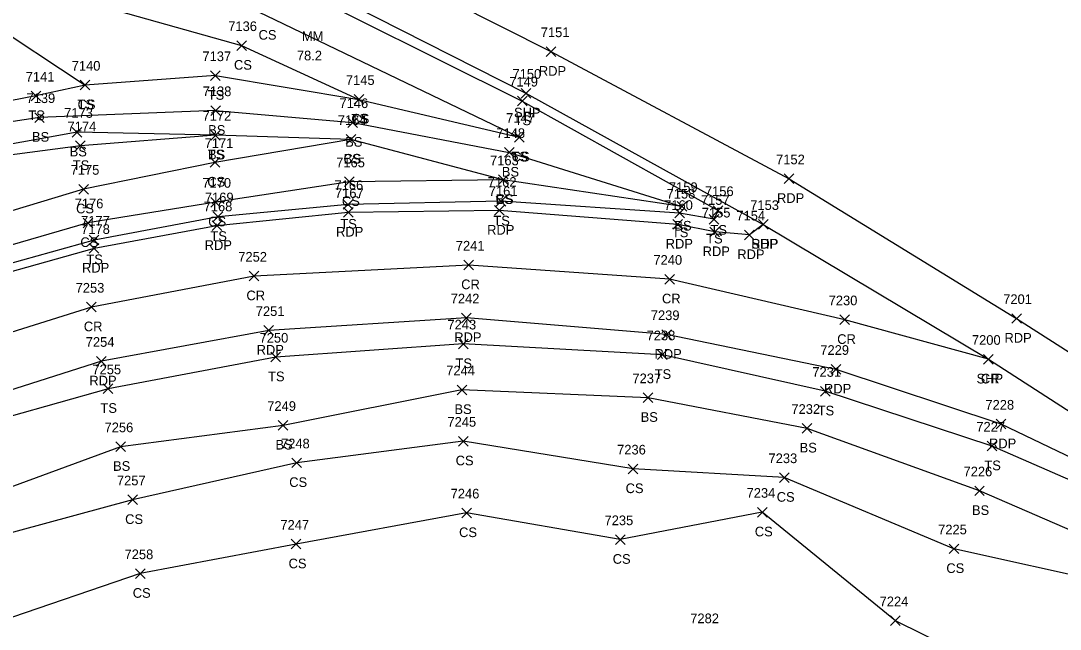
# Model space of a CAD drawing. Extents: x 1505656 to 1508446, y 700805 to 703031.
# Drawn here: x 1508114 to 1508329.4, y 701312.1 to 701438.1 of the extents above; entities that cross this region are included whole.
import ezdxf

# ---------------------------------------------------------------- set-up
doc = ezdxf.new("R2010")
doc.units = 0
for name, color, linetype in [('L_A', 7, 'Continuous'), ('L_I', 7, 'Continuous'), ('L_TIC', 7, 'Continuous'), ('LELB', 7, 'Continuous'), ('P_A', 7, 'Continuous'), ('P_I', 7, 'Continuous'), ('P_TIC', 7, 'Continuous'), ('PET', 7, 'Continuous'), ('PRC', 7, 'Continuous'), ('PSP', 7, 'Continuous'), ('S_A', 7, 'Continuous'), ('S_C', 7, 'Continuous')]:
    doc.layers.add(name, color=color, linetype=linetype)

msp = doc.modelspace()

# ---------------------------------------------------------------- linework, layer by layer
at = {"layer": 'L_TIC'}
for points in [[(1508158.76, 701432), (1508160.76, 701434)], [(1508160.76, 701432), (1508158.76, 701434)], [(1508153.35, 701425.77), (1508155.35, 701427.77)], [(1508155.35, 701425.77), (1508153.35, 701427.77)], [(1508153.35, 701425.77), (1508155.35, 701427.77)], [(1508155.35, 701425.77), (1508153.35, 701427.77)], [(1508126.36, 701423.8), (1508128.36, 701425.8)], [(1508128.36, 701423.8), (1508126.36, 701425.8)], [(1508126.36, 701423.8), (1508128.36, 701425.8)], [(1508128.36, 701423.8), (1508126.36, 701425.8)], [(1508116.18, 701421.55), (1508118.18, 701423.55)], [(1508118.18, 701421.55), (1508116.18, 701423.55)], [(1508183.08, 701420.84), (1508185.08, 701422.84)], [(1508185.08, 701420.84), (1508183.08, 701422.84)], [(1508183.08, 701420.84), (1508185.08, 701422.84)], [(1508185.08, 701420.84), (1508183.08, 701422.84)], [(1508216.92, 701420.51), (1508218.92, 701422.51)], [(1508218.92, 701420.51), (1508216.92, 701422.51)], [(1508116.91, 701417.09), (1508118.91, 701419.09)], [(1508118.91, 701417.09), (1508116.91, 701419.09)], [(1508153.4, 701418.52), (1508155.4, 701420.52)], [(1508155.4, 701418.52), (1508153.4, 701420.52)], [(1508153.4, 701418.52), (1508155.4, 701420.52)], [(1508155.4, 701418.52), (1508153.4, 701420.52)], [(1508181.8, 701416.05), (1508183.8, 701418.05)], [(1508183.8, 701416.05), (1508181.8, 701418.05)], [(1508124.71, 701414.04), (1508126.71, 701416.04)], [(1508126.71, 701414.04), (1508124.71, 701416.04)], [(1508153.37, 701413.42), (1508155.37, 701415.42)], [(1508155.37, 701413.42), (1508153.37, 701415.42)], [(1508153.37, 701413.42), (1508155.37, 701415.42)], [(1508155.37, 701413.42), (1508153.37, 701415.42)], [(1508216.28, 701413), (1508218.28, 701415)], [(1508218.28, 701413), (1508216.28, 701415)], [(1508216.28, 701413), (1508218.28, 701415)], [(1508218.28, 701413), (1508216.28, 701415)], [(1508125.4, 701411.23), (1508127.4, 701413.23)], [(1508127.4, 701411.23), (1508125.4, 701413.23)], [(1508181.44, 701412.55), (1508183.44, 701414.55)], [(1508183.44, 701412.55), (1508181.44, 701414.55)], [(1508181.44, 701412.55), (1508183.44, 701414.55)], [(1508183.44, 701412.55), (1508181.44, 701414.55)], [(1508214.23, 701409.85), (1508216.23, 701411.85)], [(1508216.23, 701409.85), (1508214.23, 701411.85)], [(1508153.24, 701407.79), (1508155.24, 701409.79)], [(1508155.24, 701407.79), (1508153.24, 701409.79)], [(1508212.98, 701404.2), (1508214.98, 701406.2)], [(1508214.98, 701404.2), (1508212.98, 701406.2)], [(1508212.98, 701404.2), (1508214.98, 701406.2)], [(1508214.98, 701404.2), (1508212.98, 701406.2)], [(1508126.05, 701402.24), (1508128.05, 701404.24)], [(1508128.05, 701402.24), (1508126.05, 701404.24)], [(1508181.11, 701403.78), (1508183.11, 701405.78)], [(1508183.11, 701403.78), (1508181.11, 701405.78)], [(1508212.52, 701399.74), (1508214.52, 701401.74)], [(1508214.52, 701399.74), (1508212.52, 701401.74)], [(1508153.42, 701399.55), (1508155.42, 701401.55)], [(1508155.42, 701399.55), (1508153.42, 701401.55)], [(1508180.82, 701399.08), (1508182.82, 701401.08)], [(1508182.82, 701399.08), (1508180.82, 701401.08)], [(1508250, 701398.68), (1508252, 701400.68)], [(1508252, 701398.68), (1508250, 701400.68)], [(1508257.5, 701397.83), (1508259.5, 701399.83)], [(1508259.5, 701397.83), (1508257.5, 701399.83)], [(1508257.5, 701397.83), (1508259.5, 701399.83)], [(1508259.5, 701397.83), (1508257.5, 701399.83)], [(1508153.92, 701396.54), (1508155.92, 701398.54)], [(1508155.92, 701396.54), (1508153.92, 701398.54)], [(1508249.51, 701397.31), (1508251.51, 701399.31)], [(1508251.51, 701397.31), (1508249.51, 701399.31)], [(1508256.61, 701396.01), (1508258.61, 701398.01)], [(1508258.61, 701396.01), (1508256.61, 701398.01)], [(1508126.94, 701395.28), (1508128.94, 701397.28)], [(1508128.94, 701395.28), (1508126.94, 701397.28)], [(1508128.22, 701391.72), (1508130.22, 701393.72)], [(1508130.22, 701391.72), (1508128.22, 701393.72)], [(1508204.68, 701370.2), (1508206.68, 701372.2)], [(1508206.68, 701370.2), (1508204.68, 701372.2)], [(1508165.85, 701367.48), (1508167.85, 701369.48)], [(1508167.85, 701367.48), (1508165.85, 701369.48)], [(1508245.94, 701367.96), (1508247.94, 701369.96)], [(1508247.94, 701367.96), (1508245.94, 701369.96)], [(1508131.13, 701360.93), (1508133.13, 701362.93)], [(1508133.13, 701360.93), (1508131.13, 701362.93)], [(1508204.43, 701360.69), (1508206.43, 701362.69)], [(1508206.43, 701360.69), (1508204.43, 701362.69)], [(1508243, 701359.07), (1508245, 701361.07)], [(1508245, 701359.07), (1508243, 701361.07)], [(1508279.7, 701360.4), (1508281.7, 701362.4)], [(1508281.7, 701360.4), (1508279.7, 701362.4)], [(1508167.36, 701353.34), (1508169.36, 701355.34)], [(1508169.36, 701353.34), (1508167.36, 701355.34)], [(1508275.93, 701352.72), (1508277.93, 701354.72)], [(1508277.93, 701352.72), (1508275.93, 701354.72)], [(1508133.71, 701348.92), (1508135.71, 701350.92)], [(1508135.71, 701348.92), (1508133.71, 701350.92)], [(1508204.68, 701350.06), (1508206.68, 701352.06)], [(1508206.68, 701350.06), (1508204.68, 701352.06)], [(1508314.24, 701349.05), (1508316.24, 701351.05)], [(1508316.24, 701349.05), (1508314.24, 701351.05)], [(1508170.2, 701345.58), (1508172.2, 701347.58)], [(1508172.2, 701345.58), (1508170.2, 701347.58)], [(1508239.89, 701344.31), (1508241.89, 701346.31)], [(1508241.89, 701344.31), (1508239.89, 701346.31)], [(1508271.19, 701342.52), (1508273.19, 701344.52)], [(1508273.19, 701342.52), (1508271.19, 701344.52)], [(1508311.64, 701339.78), (1508313.64, 701341.78)], [(1508313.64, 701339.78), (1508311.64, 701341.78)], [(1508136.21, 701337.92), (1508138.21, 701339.92)], [(1508138.21, 701337.92), (1508136.21, 701339.92)], [(1508205.39, 701335.2), (1508207.39, 701337.2)], [(1508207.39, 701335.2), (1508205.39, 701337.2)], [(1508266.65, 701335.35), (1508268.65, 701337.35)], [(1508268.65, 701335.35), (1508266.65, 701337.35)], [(1508170.07, 701328.74), (1508172.07, 701330.74)], [(1508172.07, 701328.74), (1508170.07, 701330.74)], [(1508237.22, 701329.67), (1508239.22, 701331.67)], [(1508239.22, 701329.67), (1508237.22, 701331.67)], [(1508306.33, 701327.77), (1508308.33, 701329.77)], [(1508308.33, 701327.77), (1508306.33, 701329.77)], [(1508137.79, 701322.63), (1508139.79, 701324.63)], [(1508139.79, 701322.63), (1508137.79, 701324.63)], [(1508294.21, 701312.88), (1508296.21, 701314.88)], [(1508296.21, 701312.88), (1508294.21, 701314.88)]]:
    msp.add_lwpolyline(points, dxfattribs=at)
at = {"layer": 'LELB'}
for points in [[(1507330.99, 701644.33), (1507331.57, 701641.78), (1507371.77, 701640.82), (1507418.46, 701636.99), (1507454.87, 701633.93), (1507504.71, 701630.03), (1507556.91, 701624.43), (1507606.36, 701618.24), (1507661.13, 701610.06), (1507708.24, 701601.04), (1507762.71, 701589.7), (1507814.48, 701577.03), (1507868.53, 701563.07), (1507920.81, 701547.22), (1507968.27, 701530.82), (1508018.88, 701511.91), (1508073.65, 701490), (1508121.33, 701468.38), (1508166.06, 701447.38), (1508217.92, 701421.51), (1508258.5, 701398.83)], [(1507371.82, 701631.2), (1507419.37, 701631.63), (1507454.54, 701624.79), (1507505.05, 701622.5), (1507556.06, 701615.76), (1507605.29, 701610.61), (1507659.37, 701602.95), (1507705.7, 701593), (1507760.19, 701582.5), (1507867, 701555.37), (1507918.17, 701539.42), (1507965.63, 701522.2), (1508016.59, 701504.14), (1508070.8, 701481.77), (1508118.11, 701461.28), (1508164.85, 701439.21), (1508217.28, 701414)], [(1507454.54, 701624.79), (1507504.74, 701612.91), (1507553.31, 701603.43), (1507603.85, 701602.08), (1507655.97, 701590.04), (1507703.48, 701579.9), (1507760.64, 701566.79), (1507809, 701557.31), (1507862.6, 701540.85), (1507913.87, 701525.11), (1507961.41, 701507.74), (1508011.25, 701488.42), (1508064.95, 701467.68), (1508110.8, 701446.82), (1508159.76, 701433), (1508184.08, 701421.84)], [(1507553.31, 701603.43), (1507601.29, 701589.31), (1507651.17, 701577.15), (1507700.01, 701567.77), (1507706.67, 701566.48), (1507755.13, 701548.25), (1507804.73, 701537.71), (1507857.08, 701521.39), (1507908.09, 701506.28), (1507956.13, 701490.86), (1508006.59, 701471.95), (1508058.56, 701454.54), (1508106.68, 701438.49), (1508127.36, 701424.8)], [(1508154.35, 701426.77), (1508127.36, 701424.8), (1508117.18, 701422.55), (1508087.33, 701416.79), (1508064.83, 701410.79), (1508066.66, 701419.74), (1508059.3, 701421.35), (1508054.24, 701408.37), (1508038.64, 701402.52), (1508017.45, 701393.31), (1507999.23, 701386.55), (1508004.56, 701399.96), (1508002.66, 701415), (1508002.64, 701414.99), (1507982.45, 701429.7), (1507948.4, 701442.92), (1507895.43, 701458.86), (1507841.28, 701473.44), (1507789.73, 701489.92), (1507749.11, 701498.17), (1507698.99, 701517.09)], [(1508154.4, 701419.52), (1508117.91, 701418.09), (1508089.24, 701413.76), (1508080.06, 701410.17), (1508061.42, 701406.62), (1508063.71, 701416.27), (1508061.94, 701416.78), (1508055.79, 701407.35), (1508040.19, 701400.53), (1508018.4, 701391.4), (1508000.84, 701382.32), (1507989.42, 701382.89), (1507991.8, 701393.99), (1507993.42, 701406.89), (1507988.68, 701409.34), (1507981.01, 701410.1), (1507940.5, 701420.91), (1507888, 701436.83), (1507832, 701451.94), (1507780.89, 701466.06), (1507743.18, 701476.74), (1507690.02, 701491.91)], [(1508154.35, 701426.77), (1508184.08, 701421.84), (1508217.28, 701414)], [(1508154.4, 701419.52), (1508182.8, 701417.05), (1508215.23, 701410.85), (1508251, 701399.68), (1508213.98, 701405.2), (1508182.44, 701413.55), (1508154.37, 701414.42), (1508125.71, 701415.04), (1508096.26, 701409.76), (1508073.75, 701404.93), (1508062.94, 701402.24), (1508041.57, 701393.41), (1508020.15, 701386.08), (1508000.78, 701379.38), (1507984.9, 701371.99), (1507974.85, 701354.32), (1507965.1, 701336.98)], [(1508154.37, 701414.42), (1508126.4, 701412.23), (1508096.45, 701408.26), (1508071.13, 701402.05), (1508062.75, 701400.33), (1508044.7, 701391.76), (1508020.88, 701383.6), (1508002.23, 701372.66), (1507989.78, 701369), (1507979.3, 701351.16), (1507969.45, 701332.86)], [(1508182.44, 701413.55), (1508154.24, 701408.79), (1508127.05, 701403.24), (1508100.22, 701395.21), (1508075.33, 701393.9), (1508052.69, 701378.8), (1508028.82, 701363.66)], [(1508213.98, 701405.2), (1508182.11, 701404.78), (1508154.42, 701400.55), (1508127.94, 701396.28), (1508101.95, 701388.78), (1508081.59, 701382.53), (1508058.12, 701371.27), (1508033.98, 701358.66)], [(1508258.5, 701398.83), (1508257.61, 701397.01), (1508250.51, 701398.31), (1508213.52, 701400.74), (1508181.82, 701400.08), (1508154.92, 701397.54), (1508129.22, 701392.72), (1508102.47, 701385.22), (1508082.88, 701378.2), (1508059.61, 701368.36), (1508035.53, 701355.4)], [(1508431.77, 701280.78), (1508387.5, 701311.78), (1508348.97, 701335.33), (1508315.24, 701350.05), (1508280.7, 701361.4), (1508246.94, 701368.96), (1508205.68, 701371.2), (1508166.85, 701368.48), (1508132.13, 701361.93), (1508090.91, 701350.28), (1508068.59, 701339.2), (1508045.2, 701325.84)], [(1508427.04, 701274.81), (1508383.39, 701305.02), (1508343.87, 701327.27), (1508312.64, 701340.78), (1508276.93, 701353.72), (1508244, 701360.07), (1508205.43, 701361.69), (1508168.36, 701354.34), (1508134.71, 701349.92), (1508097.62, 701336.28), (1508074.24, 701329.1), (1508053.07, 701314.95)], [(1508414.72, 701258.98), (1508371.7, 701288.23), (1508339.69, 701321.62), (1508307.33, 701328.77), (1508272.19, 701343.52), (1508240.89, 701345.31), (1508205.68, 701351.06), (1508171.2, 701346.58), (1508137.21, 701338.92), (1508101.29, 701329.16), (1508076.83, 701322.26), (1508059.02, 701305.56)], [(1508401.54, 701242.66), (1508359.95, 701269.54), (1508323.47, 701299.9), (1508295.21, 701313.88), (1508267.65, 701336.35), (1508238.22, 701330.67), (1508206.39, 701336.2), (1508171.07, 701329.74), (1508138.79, 701323.63), (1508109.62, 701313.71), (1508081.24, 701310.41), (1508068.11, 701293.32)]]:
    msp.add_lwpolyline(points, dxfattribs=at)
at = {"layer": 'P_TIC'}
for points in [[(1508222.87, 701430.74), (1508224.87, 701432.74)], [(1508224.87, 701430.74), (1508222.87, 701432.74)], [(1508217.67, 701422.12), (1508219.67, 701424.12)], [(1508219.67, 701422.12), (1508217.67, 701424.12)], [(1508272.2, 701404.41), (1508274.2, 701406.41)], [(1508274.2, 701404.41), (1508272.2, 701406.41)], [(1508212.15, 701397.84), (1508214.15, 701399.84)], [(1508214.15, 701397.84), (1508212.15, 701399.84)], [(1508180.86, 701397.44), (1508182.86, 701399.44)], [(1508182.86, 701397.44), (1508180.86, 701399.44)], [(1508153.65, 701394.67), (1508155.65, 701396.67)], [(1508155.65, 701394.67), (1508153.65, 701396.67)], [(1508249.14, 701394.96), (1508251.14, 701396.96)], [(1508251.14, 701394.96), (1508249.14, 701396.96)], [(1508256.79, 701393.39), (1508258.79, 701395.39)], [(1508258.79, 701393.39), (1508256.79, 701395.39)], [(1508266.84, 701394.95), (1508268.84, 701396.95)], [(1508268.84, 701394.95), (1508266.84, 701396.95)], [(1508266.84, 701394.95), (1508268.84, 701396.95)], [(1508268.84, 701394.95), (1508266.84, 701396.95)], [(1508263.97, 701392.77), (1508265.97, 701394.77)], [(1508265.97, 701392.77), (1508263.97, 701394.77)], [(1508128.23, 701389.98), (1508130.23, 701391.98)], [(1508130.23, 701389.98), (1508128.23, 701391.98)], [(1508205.84, 701386.54), (1508207.84, 701388.54)], [(1508207.84, 701386.54), (1508205.84, 701388.54)], [(1508161.35, 701384.25), (1508163.35, 701386.25)], [(1508163.35, 701384.25), (1508161.35, 701386.25)], [(1508247.43, 701383.6), (1508249.43, 701385.6)], [(1508249.43, 701383.6), (1508247.43, 701385.6)], [(1508127.66, 701377.83), (1508129.66, 701379.83)], [(1508129.66, 701377.83), (1508127.66, 701379.83)], [(1508205.34, 701375.59), (1508207.34, 701377.59)], [(1508207.34, 701375.59), (1508205.34, 701377.59)], [(1508283.73, 701375.21), (1508285.73, 701377.21)], [(1508285.73, 701375.21), (1508283.73, 701377.21)], [(1508319.32, 701375.47), (1508321.32, 701377.47)], [(1508321.32, 701375.47), (1508319.32, 701377.47)], [(1508164.4, 701372.99), (1508166.4, 701374.99)], [(1508166.4, 701372.99), (1508164.4, 701374.99)], [(1508246.82, 701372.14), (1508248.82, 701374.14)], [(1508248.82, 701372.14), (1508246.82, 701374.14)], [(1508129.75, 701366.61), (1508131.75, 701368.61)], [(1508131.75, 701366.61), (1508129.75, 701368.61)], [(1508313.49, 701367.02), (1508315.49, 701369.02)], [(1508315.49, 701367.02), (1508313.49, 701369.02)], [(1508313.49, 701367.02), (1508315.49, 701369.02)], [(1508315.49, 701367.02), (1508313.49, 701369.02)], [(1508281.93, 701364.94), (1508283.93, 701366.94)], [(1508283.93, 701364.94), (1508281.93, 701366.94)], [(1508316.12, 701353.6), (1508318.12, 701355.6)], [(1508318.12, 701353.6), (1508316.12, 701355.6)]]:
    msp.add_lwpolyline(points, dxfattribs=at)
at = {"layer": 'PET'}
for points in [[(1507331.09, 701648.62), (1507371.38, 701647.72), (1507419.18, 701645.9), (1507454.47, 701643.92), (1507505.5, 701639.83), (1507558.24, 701634.71), (1507608.33, 701628.44), (1507662.88, 701620.32), (1507710.96, 701611.67), (1507764.19, 701600.14), (1507816.88, 701587.97), (1507871.99, 701573.08), (1507923.59, 701557.41), (1507972.42, 701540.77), (1508022.2, 701522.45), (1508077.84, 701500.13), (1508126.28, 701479.21), (1508172.23, 701457.76), (1508223.87, 701431.74), (1508273.2, 701405.41), (1508320.32, 701376.47), (1508371.41, 701343.81), (1508408.57, 701317.59), (1508442.85, 701293.88)], [(1508267.84, 701395.95), (1508264.97, 701393.77), (1508257.79, 701394.39), (1508250.14, 701395.96), (1508213.15, 701398.84), (1508181.86, 701398.44), (1508154.65, 701395.67), (1508129.23, 701390.98), (1508103.36, 701383.73), (1508083.42, 701376.64), (1508060.29, 701366.64), (1508036.04, 701354.24)], [(1508433.77, 701283.19), (1508388.89, 701313.87), (1508350.43, 701338.64), (1508317.12, 701354.6), (1508282.93, 701365.94), (1508247.82, 701373.14), (1508206.34, 701376.59), (1508165.4, 701373.99), (1508130.75, 701367.61), (1508088.47, 701354.16), (1508065.37, 701344.9), (1508042.81, 701329.23)]]:
    msp.add_lwpolyline(points, dxfattribs=at)
at = {"layer": 'PRC'}
msp.add_lwpolyline([(1508314.49, 701368.02), (1508284.73, 701376.21), (1508248.43, 701384.6), (1508206.84, 701387.54), (1508162.35, 701385.25), (1508128.66, 701378.83), (1508083.35, 701364.58), (1508061.08, 701354.73), (1508034.54, 701339.84)], dxfattribs=at)
at = {"layer": 'PSP'}
msp.add_lwpolyline([(1507708.42, 701603.34), (1507763.41, 701591.78), (1507815.2, 701579.55), (1507869.54, 701564.45), (1507921.6, 701549.15), (1507968.74, 701532.12), (1508019.6, 701513.82), (1508074.06, 701491.08), (1508122.46, 701470.23), (1508167.01, 701449.38), (1508218.67, 701423.12), (1508267.84, 701395.95), (1508314.49, 701368.02), (1508364.92, 701335.51), (1508402.55, 701308.52), (1508433.77, 701283.19)], dxfattribs=at)

# ---------------------------------------------------------------- texts
at = {"layer": 'L_A'}
for s, p in [('CS', (1508163.29, 701434.21)), ('CS', (1508158.2, 701428)), ('TS', (1508152.76, 701421.77)), ('TS', (1508152.76, 701421.77)), ('TS', (1508125.77, 701419.8)), ('CS', (1508125.8, 701419.8)), ('TS', (1508115.59, 701417.55)), ('TS', (1508182.49, 701416.84)), ('CS', (1508182.52, 701416.84)), ('TS', (1508216.33, 701416.51)), ('BS', (1508116.35, 701413.09)), ('BS', (1508152.85, 701414.52)), ('BS', (1508152.85, 701414.52)), ('BS', (1508181.24, 701412.05)), ('BS', (1508124.16, 701410.04)), ('TS', (1508152.78, 701409.42)), ('BS', (1508152.81, 701409.42)), ('CS', (1508180.88, 701408.55)), ('BS', (1508180.88, 701408.55)), ('TS', (1508215.68, 701409)), ('CS', (1508215.72, 701409)), ('TS', (1508124.81, 701407.23)), ('BS', (1508213.68, 701405.85)), ('CS', (1508152.68, 701403.79)), ('CS', (1508180.55, 701399.78)), ('CS', (1508212.42, 701400.2)), ('BS', (1508212.42, 701400.2)), ('CS', (1508125.49, 701398.24)), ('CS', (1508152.86, 701395.55)), ('TS', (1508211.93, 701395.74)), ('TS', (1508180.23, 701395.08)), ('TS', (1508248.92, 701393.31)), ('BS', (1508249.44, 701394.68)), ('TS', (1508256.91, 701393.83)), ('TS', (1508256.91, 701393.83)), ('CS', (1508126.38, 701391.28)), ('TS', (1508153.32, 701392.54)), ('TS', (1508256.02, 701392.01)), ('TS', (1508127.63, 701387.72)), ('TS', (1508204.09, 701366.2)), ('TS', (1508165.26, 701363.48)), ('TS', (1508245.35, 701363.96)), ('TS', (1508130.54, 701356.93)), ('BS', (1508203.87, 701356.69)), ('BS', (1508242.44, 701355.07)), ('TS', (1508279.11, 701356.4)), ('BS', (1508166.8, 701349.34)), ('BS', (1508275.37, 701348.72)), ('CS', (1508204.12, 701346.06)), ('BS', (1508133.15, 701344.92)), ('TS', (1508313.65, 701345.05)), ('CS', (1508169.64, 701341.58)), ('CS', (1508239.33, 701340.31)), ('CS', (1508270.63, 701338.52)), ('BS', (1508311.08, 701335.78)), ('CS', (1508135.65, 701333.92)), ('CS', (1508204.83, 701331.2)), ('CS', (1508266.09, 701331.35)), ('CS', (1508169.51, 701324.74)), ('CS', (1508236.66, 701325.67)), ('CS', (1508305.77, 701323.77)), ('CS', (1508137.23, 701318.63))]:
    msp.add_text(s, height=2, dxfattribs=at).set_placement(p)
at = {"layer": 'L_I'}
for s, p in [('7136', (1508157.01, 701436)), ('7137', (1508151.66, 701429.77)), ('7137', (1508151.66, 701429.77)), ('7140', (1508124.58, 701427.8)), ('7140', (1508124.58, 701427.8)), ('7141', (1508115.06, 701425.55)), ('7145', (1508181.38, 701424.84)), ('7145', (1508181.38, 701424.84)), ('7149', (1508215.22, 701424.51)), ('7138', (1508151.71, 701422.52)), ('7138', (1508151.71, 701422.52)), ('7139', (1508115.21, 701421.09)), ('7146', (1508180.05, 701420.05)), ('7173', (1508123.02, 701418.04)), ('7172', (1508151.68, 701417.42)), ('7172', (1508151.68, 701417.42)), ('7147', (1508214.58, 701417)), ('7147', (1508214.58, 701417)), ('7174', (1508123.71, 701415.23)), ('7164', (1508179.7, 701416.55)), ('7164', (1508179.7, 701416.55)), ('7148', (1508212.54, 701413.85)), ('7171', (1508152.12, 701411.79)), ('7175', (1508124.36, 701406.24)), ('7165', (1508179.37, 701407.78)), ('7163', (1508211.24, 701408.2)), ('7163', (1508211.24, 701408.2)), ('7170', (1508151.64, 701403.55)), ('7166', (1508179.02, 701403.08)), ('7162', (1508210.78, 701403.74)), ('7159', (1508248.3, 701402.68)), ('7156', (1508255.76, 701401.83)), ('7156', (1508255.76, 701401.83)), ('7169', (1508152.17, 701400.54)), ('7158', (1508247.82, 701401.31)), ('7157', (1508254.92, 701400.01)), ('7176', (1508125.19, 701399.28)), ('7177', (1508126.53, 701395.72)), ('7243', (1508202.42, 701374.2)), ('7238', (1508243.68, 701371.96)), ('7250', (1508163.5, 701371.48)), ('7255', (1508128.87, 701364.93)), ('7244', (1508202.17, 701364.69)), ('7237', (1508240.74, 701363.07)), ('7231', (1508278.01, 701364.4)), ('7249', (1508165.09, 701357.34)), ('7232', (1508273.67, 701356.72)), ('7256', (1508131.39, 701352.92)), ('7245', (1508202.42, 701354.06)), ('7227', (1508311.98, 701353.05)), ('7248', (1508167.94, 701349.58)), ('7236', (1508237.57, 701348.31)), ('7233', (1508268.93, 701346.52)), ('7226', (1508309.33, 701343.78)), ('7257', (1508133.95, 701341.92)), ('7234', (1508264.39, 701339.35)), ('7246', (1508203.08, 701339.2)), ('7235', (1508234.96, 701333.67)), ('7247', (1508167.81, 701332.74)), ('7225', (1508304.07, 701331.77)), ('7258', (1508135.53, 701326.63)), ('7224', (1508291.95, 701316.88)), ('7282', (1508252.72, 701313.37))]:
    msp.add_text(s, height=2, dxfattribs=at).set_placement(p)
at = {"layer": 'P_A'}
for s, p in [('RDP', (1508221.36, 701426.74)), ('SHP', (1508216.21, 701418.12)), ('RDP', (1508270.68, 701400.41)), ('RDP', (1508179.35, 701393.44)), ('RDP', (1508210.64, 701393.84)), ('RDP', (1508152.13, 701390.67)), ('RDP', (1508247.63, 701390.96)), ('RDP', (1508255.28, 701389.39)), ('SHP', (1508265.38, 701390.95)), ('RDP', (1508265.33, 701390.95)), ('RDP', (1508262.46, 701388.77)), ('RDP', (1508126.72, 701385.98)), ('CR', (1508205.27, 701382.54)), ('CR', (1508160.78, 701380.25)), ('CR', (1508246.86, 701379.6)), ('CR', (1508127.09, 701373.83)), ('RDP', (1508203.83, 701371.59)), ('CR', (1508283.16, 701371.21)), ('RDP', (1508317.81, 701371.47)), ('RDP', (1508162.89, 701368.99)), ('RDP', (1508245.31, 701368.14)), ('SHP', (1508312.03, 701363.02)), ('CR', (1508312.92, 701363.02)), ('RDP', (1508128.24, 701362.61)), ('RDP', (1508280.42, 701360.94)), ('RDP', (1508314.61, 701349.6))]:
    msp.add_text(s, height=2, dxfattribs=at).set_placement(p)
at = {"layer": 'P_I'}
for s, p in [('7151', (1508221.75, 701434.74)), ('7150', (1508215.89, 701426.12)), ('7152', (1508270.5, 701408.41)), ('7161', (1508210.98, 701401.84)), ('7167', (1508179.12, 701401.44)), ('7168', (1508151.91, 701398.67)), ('7160', (1508247.31, 701398.96)), ('7153', (1508265.15, 701398.95)), ('7153', (1508265.15, 701398.95)), ('7155', (1508255.1, 701397.39)), ('7154', (1508262.28, 701396.77)), ('7178', (1508126.54, 701393.98)), ('7241', (1508204.15, 701390.54)), ('7252', (1508159.09, 701388.25)), ('7240', (1508245.09, 701387.6)), ('7253', (1508125.4, 701381.83)), ('7242', (1508203.09, 701379.59)), ('7230', (1508281.39, 701379.21)), ('7201', (1508317.55, 701379.47)), ('7251', (1508162.71, 701376.99)), ('7239', (1508244.55, 701376.14)), ('7254', (1508127.49, 701370.61)), ('7200', (1508311.07, 701371.02)), ('7200', (1508311.07, 701371.02)), ('7229', (1508279.66, 701368.94)), ('7228', (1508313.86, 701357.6))]:
    msp.add_text(s, height=2, dxfattribs=at).set_placement(p)
at = {"layer": 'S_A'}
msp.add_text('MM', height=2, dxfattribs=at).set_placement((1508172.27, 701433.93))
at = {"layer": 'S_C'}
msp.add_text('78.2', height=2, dxfattribs=at).set_placement((1508171.23, 701429.93))

doc.saveas('drawing.dxf')
